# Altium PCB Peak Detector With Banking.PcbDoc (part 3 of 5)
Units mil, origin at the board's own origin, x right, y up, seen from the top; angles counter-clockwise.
Board outline 3330 x 2725 mil, 4 copper layers (TopLayer, GROUND, MidLayer1, BottomLayer); 549 components, 391 nets, 1594 pads, 460 vias.
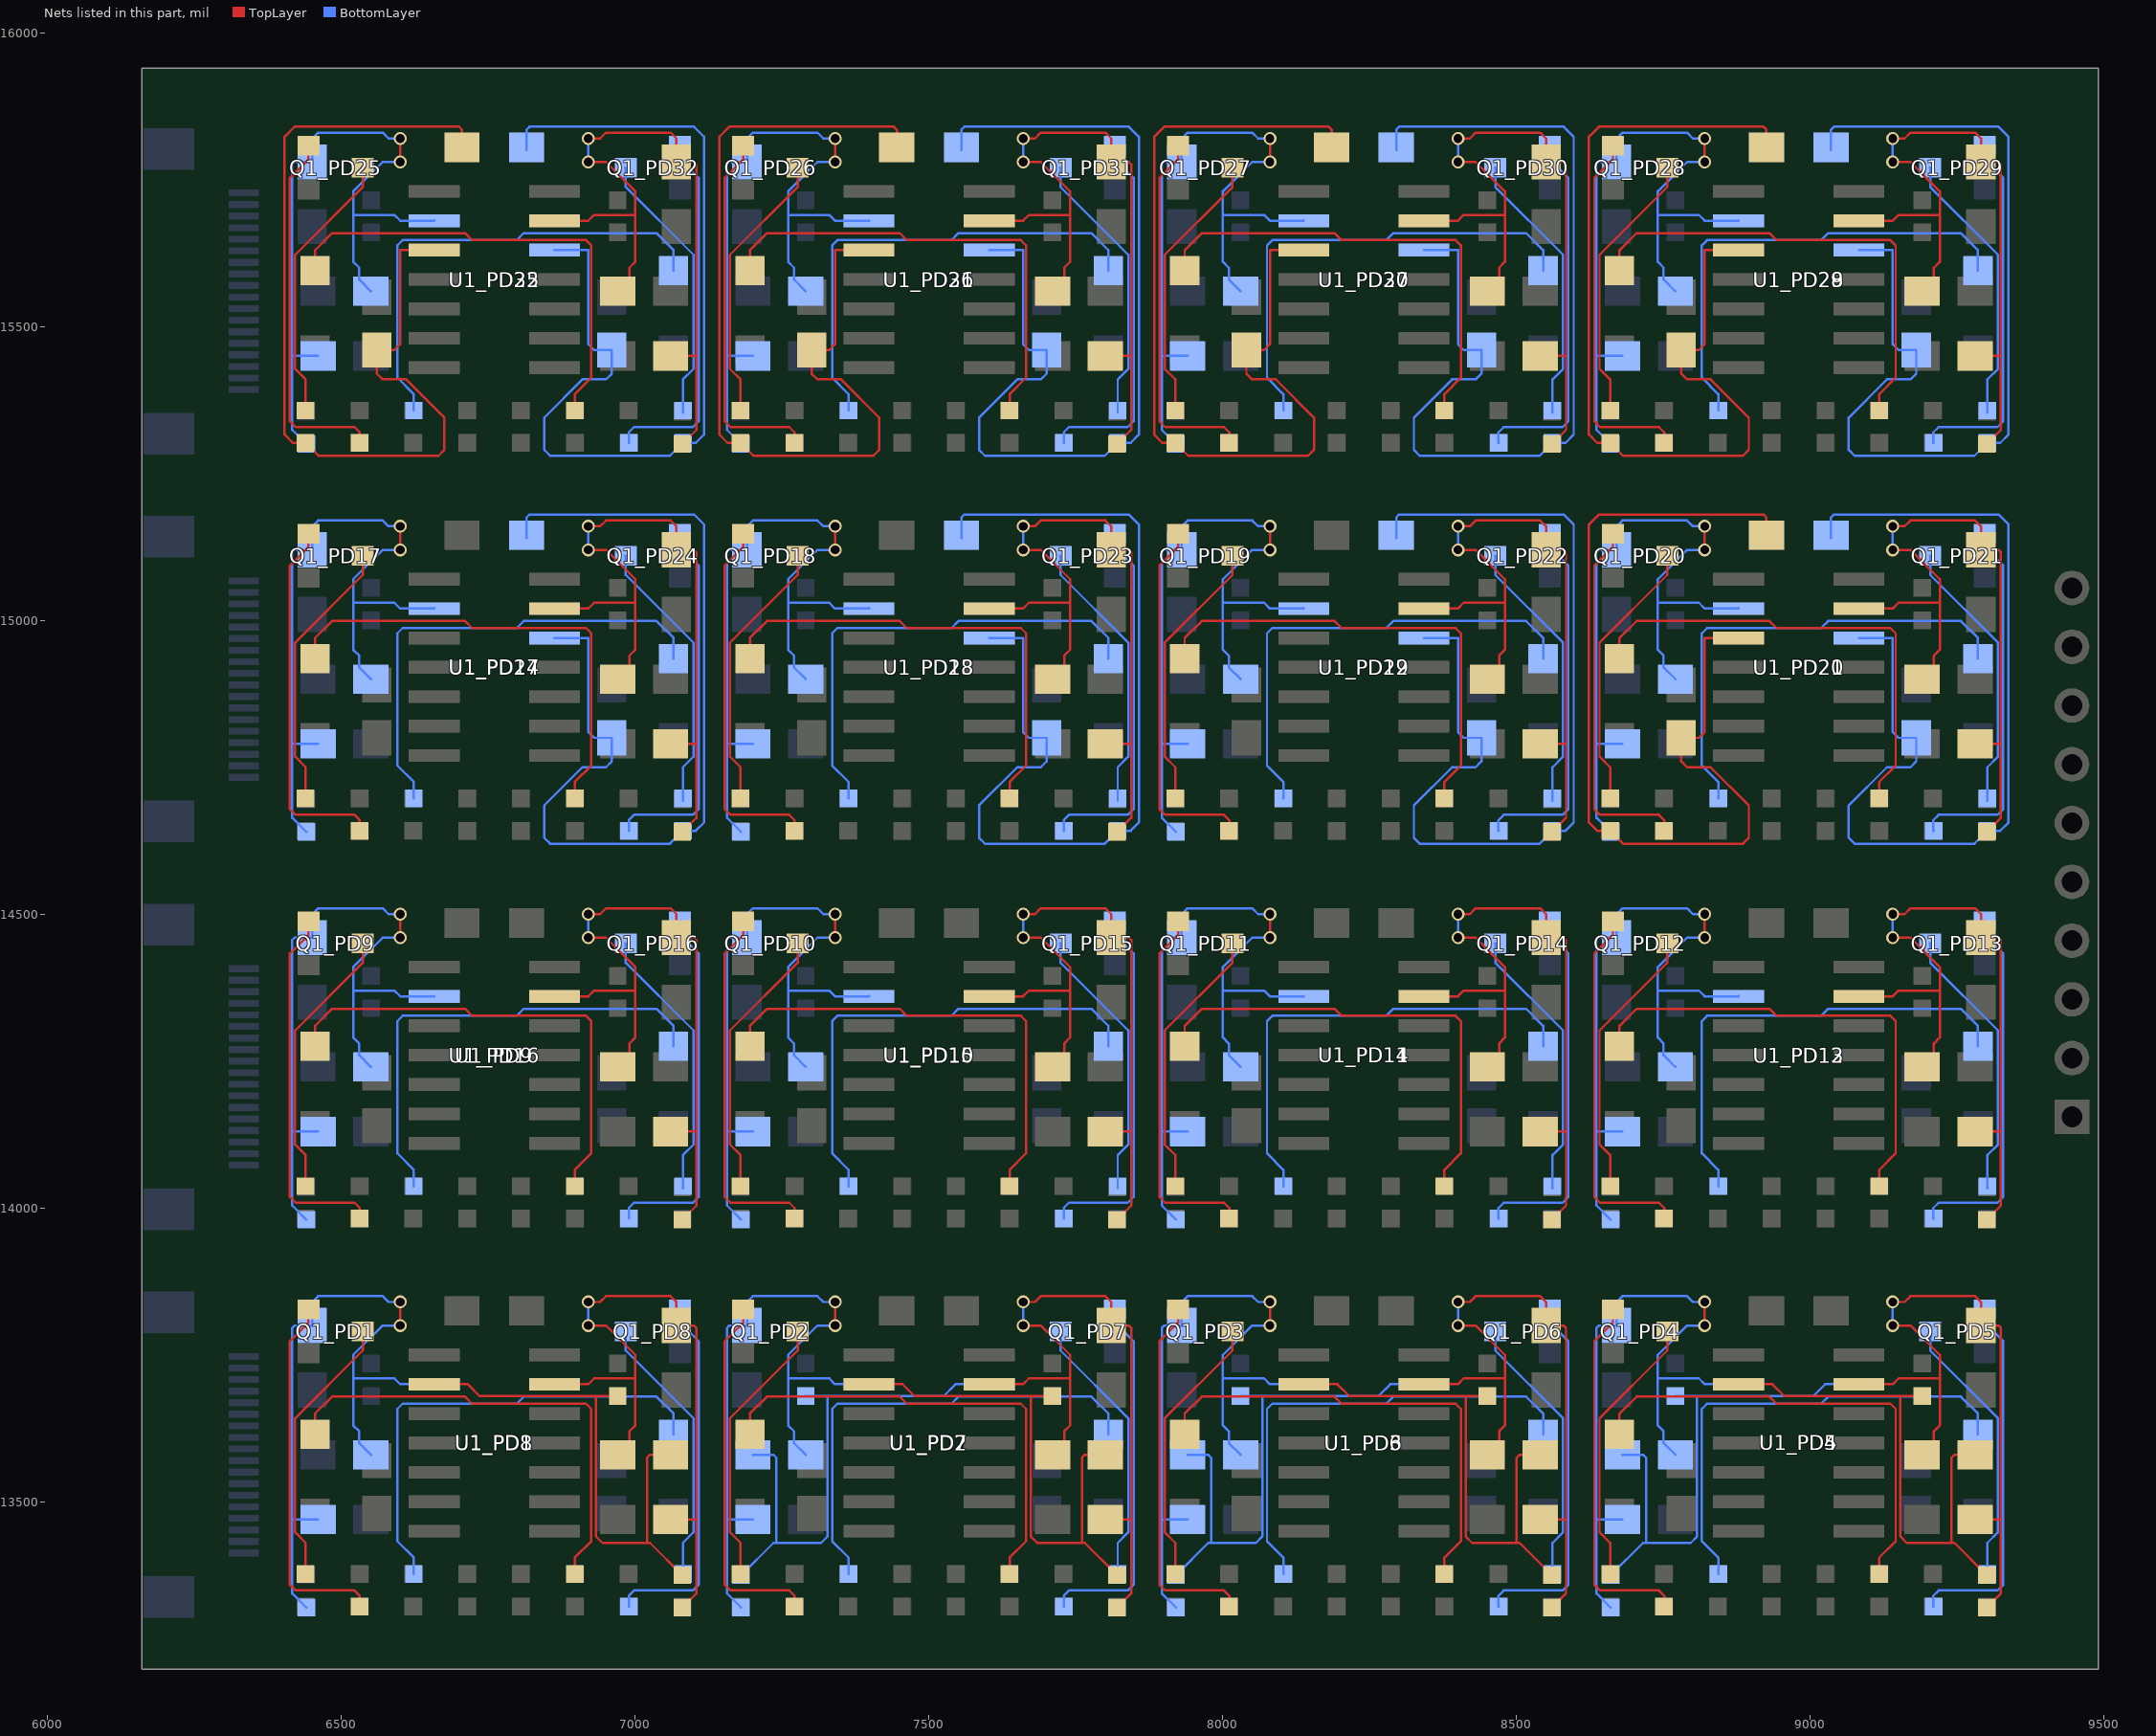
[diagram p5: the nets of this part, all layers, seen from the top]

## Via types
v1: diameter 22, hole 15, TopLayer to BottomLayer, 432 vias
v2: diameter 22, hole 16, TopLayer to BottomLayer, 28 vias

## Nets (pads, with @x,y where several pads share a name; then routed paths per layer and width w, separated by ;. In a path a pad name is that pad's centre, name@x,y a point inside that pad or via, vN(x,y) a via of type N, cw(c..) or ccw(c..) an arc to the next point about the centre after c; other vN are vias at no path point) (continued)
N6_PD20: C6_PD20.2 D1_PD20.2 R5_PD20.1 U1_PD20.10 | length 1647
  TopLayer w4: U1_PD20.10@8877.63,14970 8820,14970 8820,14810 8810,14800 C6_PD20.2@8780,14799.99 8780,14760 8790,14750 8830,14750 8895,14685 8895,14630 8885,14620 8681,14620 R5_PD20.1@8659,14642 8637,14642 8623,14656 8623,15163 8640,15180 8920,15180 8925.01,15174.99 D1_PD20.2@8925.01,15145 D1_PD20.2@8925.01,15140
N6_PD21: C6_PD21.2 D1_PD21.2 R5_PD21.1 U1_PD21.10 | length 1647
  BottomLayer w4: D1_PD21.2@9034.99,15140 D1_PD21.2@9034.99,15145 9034.99,15174.99 9040,15180 9320,15180 9337,15163 9337,14656 9323,14642 R5_PD21.1@9301,14642 9279,14620 9075,14620 9065,14630 9065,14685 9130,14750 9170,14750 9180,14760 C6_PD21.2@9180,14799.99 9150,14800 9140,14810 9140,14970 U1_PD21.10@9082.37,14970
N6_PD22: C6_PD22.2 D1_PD22.2 R5_PD22.1 U1_PD22.10 | length 1647
  BottomLayer w4: D1_PD22.2@8294.99,15140 D1_PD22.2@8294.99,15145 8294.99,15174.99 8300,15180 8580,15180 8597,15163 8597,14656 8583,14642 R5_PD22.1@8561,14642 8539,14620 8335,14620 8325,14630 8325,14685 8390,14750 8430,14750 8440,14760 C6_PD22.2@8440,14799.99 8410,14800 8400,14810 8400,14970 U1_PD22.10@8342.37,14970
N6_PD23: C6_PD23.2 D1_PD23.2 R5_PD23.1 U1_PD23.10 | length 1647
  BottomLayer w4: D1_PD23.2@7554.99,15140 D1_PD23.2@7554.99,15145 7554.99,15174.99 7560,15180 7840,15180 7857,15163 7857,14656 7843,14642 R5_PD23.1@7821,14642 7799,14620 7595,14620 7585,14630 7585,14685 7650,14750 7690,14750 7700,14760 C6_PD23.2@7700,14799.99 7670,14800 7660,14810 7660,14970 U1_PD23.10@7602.37,14970
N6_PD24: C6_PD24.2 D1_PD24.2 R5_PD24.1 U1_PD24.10 | length 1647
  BottomLayer w4: D1_PD24.2@6814.99,15140 D1_PD24.2@6814.99,15145 6814.99,15174.99 6820,15180 7100,15180 7117,15163 7117,14656 7103,14642 R5_PD24.1@7081,14642 7059,14620 6855,14620 6845,14630 6845,14685 6910,14750 6950,14750 6960,14760 C6_PD24.2@6960,14799.99 6930,14800 6920,14810 6920,14970 U1_PD24.10@6862.37,14970
N6_PD25: C6_PD25.2 D1_PD25.2 R5_PD25.1 U1_PD25.10 | length 1647
  TopLayer w4: U1_PD25.10@6657.63,15630 6600,15630 6600,15470 6590,15460 C6_PD25.2@6560,15459.99 6560,15420 6570,15410 6610,15410 6675,15345 6675,15290 6665,15280 6461,15280 R5_PD25.1@6439,15302 6417,15302 6403,15316 6403,15823 6420,15840 6700,15840 6705.01,15834.99 D1_PD25.2@6705.01,15805 D1_PD25.2@6705.01,15800
N6_PD26: C6_PD26.2 D1_PD26.2 R5_PD26.1 U1_PD26.10 | length 1647
  TopLayer w4: U1_PD26.10@7397.63,15630 7340,15630 7340,15470 7330,15460 C6_PD26.2@7300,15459.99 7300,15420 7310,15410 7350,15410 7415,15345 7415,15290 7405,15280 7201,15280 R5_PD26.1@7179,15302 7157,15302 7143,15316 7143,15823 7160,15840 7440,15840 7445.01,15834.99 D1_PD26.2@7445.01,15805 D1_PD26.2@7445.01,15800
N6_PD27: C6_PD27.2 D1_PD27.2 R5_PD27.1 U1_PD27.10 | length 1647
  TopLayer w4: U1_PD27.10@8137.63,15630 8080,15630 8080,15470 8070,15460 C6_PD27.2@8040,15459.99 8040,15420 8050,15410 8090,15410 8155,15345 8155,15290 8145,15280 7941,15280 R5_PD27.1@7919,15302 7897,15302 7883,15316 7883,15823 7900,15840 8180,15840 8185.01,15834.99 D1_PD27.2@8185.01,15805 D1_PD27.2@8185.01,15800
N6_PD28: C6_PD28.2 D1_PD28.2 R5_PD28.1 U1_PD28.10 | length 1647
  TopLayer w4: U1_PD28.10@8877.63,15630 8820,15630 8820,15470 8810,15460 C6_PD28.2@8780,15459.99 8780,15420 8790,15410 8830,15410 8895,15345 8895,15290 8885,15280 8681,15280 R5_PD28.1@8659,15302 8637,15302 8623,15316 8623,15823 8640,15840 8920,15840 8925.01,15834.99 D1_PD28.2@8925.01,15805 D1_PD28.2@8925.01,15800
N6_PD29: C6_PD29.2 D1_PD29.2 R5_PD29.1 U1_PD29.10 | length 1647
  BottomLayer w4: D1_PD29.2@9034.99,15800 D1_PD29.2@9034.99,15805 9034.99,15834.99 9040,15840 9320,15840 9337,15823 9337,15316 9323,15302 R5_PD29.1@9301,15302 9279,15280 9075,15280 9065,15290 9065,15345 9130,15410 9170,15410 9180,15420 C6_PD29.2@9180,15459.99 9150,15460 9140,15470 9140,15630 U1_PD29.10@9082.37,15630
N6_PD30: C6_PD30.2 D1_PD30.2 R5_PD30.1 U1_PD30.10 | length 1647
  BottomLayer w4: D1_PD30.2@8294.99,15800 D1_PD30.2@8294.99,15805 8294.99,15834.99 8300,15840 8580,15840 8597,15823 8597,15316 8583,15302 R5_PD30.1@8561,15302 8539,15280 8335,15280 8325,15290 8325,15345 8390,15410 8430,15410 8440,15420 C6_PD30.2@8440,15459.99 8410,15460 8400,15470 8400,15630 U1_PD30.10@8342.37,15630
N6_PD31: C6_PD31.2 D1_PD31.2 R5_PD31.1 U1_PD31.10 | length 1647
  BottomLayer w4: D1_PD31.2@7554.99,15800 D1_PD31.2@7554.99,15805 7554.99,15834.99 7560,15840 7840,15840 7857,15823 7857,15316 7843,15302 R5_PD31.1@7821,15302 7799,15280 7595,15280 7585,15290 7585,15345 7650,15410 7690,15410 7700,15420 C6_PD31.2@7700,15459.99 7670,15460 7660,15470 7660,15630 U1_PD31.10@7602.37,15630
N6_PD32: C6_PD32.2 D1_PD32.2 R5_PD32.1 U1_PD32.10 | length 1647
  BottomLayer w4: D1_PD32.2@6814.99,15800 D1_PD32.2@6814.99,15805 6814.99,15834.99 6820,15840 7100,15840 7117,15823 7117,15316 7103,15302 R5_PD32.1@7081,15302 7059,15280 6855,15280 6845,15290 6845,15345 6910,15410 6950,15410 6960,15420 C6_PD32.2@6960,15459.99 6930,15460 6920,15470 6920,15630 U1_PD32.10@6862.37,15630
N7_PD1: Q1_PD1.2 R4_PD1.2 | length 626.9
  TopLayer w4: Q1_PD1.2@6443.74,13827.4 6443.74,13804.74 6412,13773 6412,13359 6422,13349 6522,13349 6531,13340 6531,13321.99 R4_PD1.2@6530.57,13321.99
N7_PD2: Q1_PD2.2 R4_PD2.2 | length 626.9
  TopLayer w4: Q1_PD2.2@7183.74,13827.4 7183.74,13804.74 7152,13773 7152,13359 7162,13349 7262,13349 7271,13340 7271,13321.99 R4_PD2.2@7270.57,13321.99
N7_PD3: Q1_PD3.2 R4_PD3.2 | length 626.9
  TopLayer w4: Q1_PD3.2@7923.74,13827.4 7923.74,13804.74 7892,13773 7892,13359 7902,13349 8002,13349 8011,13340 8011,13321.99 R4_PD3.2@8010.57,13321.99
N7_PD4: Q1_PD4.2 R4_PD4.2 | length 626.9
  TopLayer w4: Q1_PD4.2@8663.74,13827.4 8663.74,13804.74 8632,13773 8632,13359 8642,13349 8742,13349 8751,13340 8751,13321.99 R4_PD4.2@8750.57,13321.99
N7_PD5: Q1_PD5.2 R4_PD5.2 | length 626.9
  BottomLayer w4: R4_PD5.2@9209.43,13321.99 9209,13321.99 9209,13340 9218,13349 9318,13349 9328,13359 9328,13773 9296.26,13804.74 Q1_PD5.2@9296.26,13827.4
N7_PD6: Q1_PD6.2 R4_PD6.2 | length 626.9
  BottomLayer w4: R4_PD6.2@8469.43,13321.99 8469,13321.99 8469,13340 8478,13349 8578,13349 8588,13359 8588,13773 8556.26,13804.74 Q1_PD6.2@8556.26,13827.4
N7_PD7: Q1_PD7.2 R4_PD7.2 | length 626.9
  BottomLayer w4: R4_PD7.2@7729.43,13321.99 7729,13321.99 7729,13340 7738,13349 7838,13349 7848,13359 7848,13773 7816.26,13804.74 Q1_PD7.2@7816.26,13827.4
N7_PD8: Q1_PD8.2 R4_PD8.2 | length 626.9
  BottomLayer w4: R4_PD8.2@6989.43,13321.99 6989,13321.99 6989,13340 6998,13349 7098,13349 7108,13359 7108,13773 7076.26,13804.74 Q1_PD8.2@7076.26,13827.4
N7_PD9: Q1_PD9.2 R4_PD9.2 | length 626.9
  TopLayer w4: Q1_PD9.2@6443.74,14487.4 6443.74,14464.74 6412,14433 6412,14019 6422,14009 6522,14009 6531,14000 6531,13981.99 R4_PD9.2@6530.57,13981.99
N7_PD10: Q1_PD10.2 R4_PD10.2 | length 626.9
  TopLayer w4: Q1_PD10.2@7183.74,14487.4 7183.74,14464.74 7152,14433 7152,14019 7162,14009 7262,14009 7271,14000 7271,13981.99 R4_PD10.2@7270.57,13981.99
N7_PD11: Q1_PD11.2 R4_PD11.2 | length 626.9
  TopLayer w4: Q1_PD11.2@7923.74,14487.4 7923.74,14464.74 7892,14433 7892,14019 7902,14009 8002,14009 8011,14000 8011,13981.99 R4_PD11.2@8010.57,13981.99
N7_PD12: Q1_PD12.2 R4_PD12.2 | length 626.9
  TopLayer w4: Q1_PD12.2@8663.74,14487.4 8663.74,14464.74 8632,14433 8632,14019 8642,14009 8742,14009 8751,14000 8751,13981.99 R4_PD12.2@8750.57,13981.99
N7_PD13: Q1_PD13.2 R4_PD13.2 | length 626.9
  BottomLayer w4: R4_PD13.2@9209.43,13981.99 9209,13981.99 9209,14000 9218,14009 9318,14009 9328,14019 9328,14433 9296.26,14464.74 Q1_PD13.2@9296.26,14487.4
N7_PD14: Q1_PD14.2 R4_PD14.2 | length 626.9
  BottomLayer w4: R4_PD14.2@8469.43,13981.99 8469,13981.99 8469,14000 8478,14009 8578,14009 8588,14019 8588,14433 8556.26,14464.74 Q1_PD14.2@8556.26,14487.4
N7_PD15: Q1_PD15.2 R4_PD15.2 | length 626.9
  BottomLayer w4: R4_PD15.2@7729.43,13981.99 7729,13981.99 7729,14000 7738,14009 7838,14009 7848,14019 7848,14433 7816.26,14464.74 Q1_PD15.2@7816.26,14487.4
N7_PD16: Q1_PD16.2 R4_PD16.2 | length 626.9
  BottomLayer w4: R4_PD16.2@6989.43,13981.99 6989,13981.99 6989,14000 6998,14009 7098,14009 7108,14019 7108,14433 7076.26,14464.74 Q1_PD16.2@7076.26,14487.4
N7_PD17: Q1_PD17.2 R4_PD17.2 | length 626.9
  TopLayer w4: Q1_PD17.2@6443.74,15147.4 6443.74,15124.74 6412,15093 6412,14679 6422,14669 6522,14669 6531,14660 6531,14641.99 R4_PD17.2@6530.57,14641.99
N7_PD18: Q1_PD18.2 R4_PD18.2 | length 626.9
  TopLayer w4: Q1_PD18.2@7183.74,15147.4 7183.74,15124.74 7152,15093 7152,14679 7162,14669 7262,14669 7271,14660 7271,14641.99 R4_PD18.2@7270.57,14641.99
N7_PD19: Q1_PD19.2 R4_PD19.2 | length 626.9
  TopLayer w4: Q1_PD19.2@7923.74,15147.4 7923.74,15124.74 7892,15093 7892,14679 7902,14669 8002,14669 8011,14660 8011,14641.99 R4_PD19.2@8010.57,14641.99
N7_PD20: Q1_PD20.2 R4_PD20.2 | length 626.9
  TopLayer w4: Q1_PD20.2@8663.74,15147.4 8663.74,15124.74 8632,15093 8632,14679 8642,14669 8742,14669 8751,14660 8751,14641.99 R4_PD20.2@8750.57,14641.99
N7_PD21: Q1_PD21.2 R4_PD21.2 | length 626.9
  BottomLayer w4: R4_PD21.2@9209.43,14641.99 9209,14641.99 9209,14660 9218,14669 9318,14669 9328,14679 9328,15093 9296.26,15124.74 Q1_PD21.2@9296.26,15147.4
N7_PD22: Q1_PD22.2 R4_PD22.2 | length 626.9
  BottomLayer w4: R4_PD22.2@8469.43,14641.99 8469,14641.99 8469,14660 8478,14669 8578,14669 8588,14679 8588,15093 8556.26,15124.74 Q1_PD22.2@8556.26,15147.4
N7_PD23: Q1_PD23.2 R4_PD23.2 | length 626.9
  BottomLayer w4: R4_PD23.2@7729.43,14641.99 7729,14641.99 7729,14660 7738,14669 7838,14669 7848,14679 7848,15093 7816.26,15124.74 Q1_PD23.2@7816.26,15147.4
N7_PD24: Q1_PD24.2 R4_PD24.2 | length 626.9
  BottomLayer w4: R4_PD24.2@6989.43,14641.99 6989,14641.99 6989,14660 6998,14669 7098,14669 7108,14679 7108,15093 7076.26,15124.74 Q1_PD24.2@7076.26,15147.4
N7_PD25: Q1_PD25.2 R4_PD25.2 | length 626.9
  TopLayer w4: Q1_PD25.2@6443.74,15807.4 6443.74,15784.74 6412,15753 6412,15339 6422,15329 6522,15329 6531,15320 6531,15301.99 R4_PD25.2@6530.57,15301.99
N7_PD26: Q1_PD26.2 R4_PD26.2 | length 626.9
  TopLayer w4: Q1_PD26.2@7183.74,15807.4 7183.74,15784.74 7152,15753 7152,15339 7162,15329 7262,15329 7271,15320 7271,15301.99 R4_PD26.2@7270.57,15301.99
N7_PD27: Q1_PD27.2 R4_PD27.2 | length 626.9
  TopLayer w4: Q1_PD27.2@7923.74,15807.4 7923.74,15784.74 7892,15753 7892,15339 7902,15329 8002,15329 8011,15320 8011,15301.99 R4_PD27.2@8010.57,15301.99
N7_PD28: Q1_PD28.2 R4_PD28.2 | length 626.9
  TopLayer w4: Q1_PD28.2@8663.74,15807.4 8663.74,15784.74 8632,15753 8632,15339 8642,15329 8742,15329 8751,15320 8751,15301.99 R4_PD28.2@8750.57,15301.99
N7_PD29: Q1_PD29.2 R4_PD29.2 | length 626.9
  BottomLayer w4: R4_PD29.2@9209.43,15301.99 9209,15301.99 9209,15320 9218,15329 9318,15329 9328,15339 9328,15753 9296.26,15784.74 Q1_PD29.2@9296.26,15807.4
N7_PD30: Q1_PD30.2 R4_PD30.2 | length 626.9
  BottomLayer w4: R4_PD30.2@8469.43,15301.99 8469,15301.99 8469,15320 8478,15329 8578,15329 8588,15339 8588,15753 8556.26,15784.74 Q1_PD30.2@8556.26,15807.4
N7_PD31: Q1_PD31.2 R4_PD31.2 | length 626.9
  BottomLayer w4: R4_PD31.2@7729.43,15301.99 7729,15301.99 7729,15320 7738,15329 7838,15329 7848,15339 7848,15753 7816.26,15784.74 Q1_PD31.2@7816.26,15807.4
N7_PD32: Q1_PD32.2 R4_PD32.2 | length 626.9
  BottomLayer w4: R4_PD32.2@6989.43,15301.99 6989,15301.99 6989,15320 6998,15329 7098,15329 7108,15339 7108,15753 7076.26,15784.74 Q1_PD32.2@7076.26,15807.4
N8_PD1: Q1_PD1.1 R5_PD1.2 | length 472.9
  TopLayer w4: R5_PD1.2@6439,13373 R5_PD1.2@6439,13377 6439,13430 6421,13448 6421,13642 6536.26,13757.26 Q1_PD1.1@6536.26,13790 Q1_PD1.1@6537,13790
N8_PD2: Q1_PD2.1 R5_PD2.2 | length 472.9
  TopLayer w4: R5_PD2.2@7179,13373 R5_PD2.2@7179,13377 7179,13430 7161,13448 7161,13642 7276.26,13757.26 Q1_PD2.1@7276.26,13790 Q1_PD2.1@7277,13790
N8_PD3: Q1_PD3.1 R5_PD3.2 | length 472.9
  TopLayer w4: R5_PD3.2@7919,13373 R5_PD3.2@7919,13377 7919,13430 7901,13448 7901,13642 8016.26,13757.26 Q1_PD3.1@8016.26,13790 Q1_PD3.1@8017,13790
N8_PD4: Q1_PD4.1 R5_PD4.2 | length 472.9
  TopLayer w4: R5_PD4.2@8659,13373 R5_PD4.2@8659,13377 8659,13430 8641,13448 8641,13642 8756.26,13757.26 Q1_PD4.1@8756.26,13790 Q1_PD4.1@8757,13790
N8_PD5: Q1_PD5.1 R5_PD5.2 | length 472.9
  BottomLayer w4: Q1_PD5.1@9203,13790 Q1_PD5.1@9203.74,13790 9203.74,13757.26 9319,13642 9319,13448 9301,13430 R5_PD5.2@9301,13377 R5_PD5.2@9301,13373
N8_PD6: Q1_PD6.1 R5_PD6.2 | length 472.9
  BottomLayer w4: Q1_PD6.1@8463,13790 Q1_PD6.1@8463.74,13790 8463.74,13757.26 8579,13642 8579,13448 8561,13430 R5_PD6.2@8561,13377 R5_PD6.2@8561,13373
N8_PD7: Q1_PD7.1 R5_PD7.2 | length 472.9
  BottomLayer w4: Q1_PD7.1@7723,13790 Q1_PD7.1@7723.74,13790 7723.74,13757.26 7839,13642 7839,13448 7821,13430 R5_PD7.2@7821,13377 R5_PD7.2@7821,13373
N8_PD8: Q1_PD8.1 R5_PD8.2 | length 472.9
  BottomLayer w4: Q1_PD8.1@6983,13790 Q1_PD8.1@6983.74,13790 6983.74,13757.26 7099,13642 7099,13448 7081,13430 R5_PD8.2@7081,13377 R5_PD8.2@7081,13373
N8_PD9: Q1_PD9.1 R5_PD9.2 | length 472.9
  TopLayer w4: R5_PD9.2@6439,14033 R5_PD9.2@6439,14037 6439,14090 6421,14108 6421,14302 6536.26,14417.26 Q1_PD9.1@6536.26,14450 Q1_PD9.1@6537,14450
N8_PD10: Q1_PD10.1 R5_PD10.2 | length 472.9
  TopLayer w4: R5_PD10.2@7179,14033 R5_PD10.2@7179,14037 7179,14090 7161,14108 7161,14302 7276.26,14417.26 Q1_PD10.1@7276.26,14450 Q1_PD10.1@7277,14450
N8_PD11: Q1_PD11.1 R5_PD11.2 | length 472.9
  TopLayer w4: R5_PD11.2@7919,14033 R5_PD11.2@7919,14037 7919,14090 7901,14108 7901,14302 8016.26,14417.26 Q1_PD11.1@8016.26,14450 Q1_PD11.1@8017,14450
N8_PD12: Q1_PD12.1 R5_PD12.2 | length 472.9
  TopLayer w4: R5_PD12.2@8659,14033 R5_PD12.2@8659,14037 8659,14090 8641,14108 8641,14302 8756.26,14417.26 Q1_PD12.1@8756.26,14450 Q1_PD12.1@8757,14450
N8_PD13: Q1_PD13.1 R5_PD13.2 | length 472.9
  BottomLayer w4: Q1_PD13.1@9203,14450 Q1_PD13.1@9203.74,14450 9203.74,14417.26 9319,14302 9319,14108 9301,14090 R5_PD13.2@9301,14037 R5_PD13.2@9301,14033
N8_PD14: Q1_PD14.1 R5_PD14.2 | length 472.9
  BottomLayer w4: Q1_PD14.1@8463,14450 Q1_PD14.1@8463.74,14450 8463.74,14417.26 8579,14302 8579,14108 8561,14090 R5_PD14.2@8561,14037 R5_PD14.2@8561,14033
N8_PD15: Q1_PD15.1 R5_PD15.2 | length 472.9
  BottomLayer w4: Q1_PD15.1@7723,14450 Q1_PD15.1@7723.74,14450 7723.74,14417.26 7839,14302 7839,14108 7821,14090 R5_PD15.2@7821,14037 R5_PD15.2@7821,14033
N8_PD16: Q1_PD16.1 R5_PD16.2 | length 472.9
  BottomLayer w4: Q1_PD16.1@6983,14450 Q1_PD16.1@6983.74,14450 6983.74,14417.26 7099,14302 7099,14108 7081,14090 R5_PD16.2@7081,14037 R5_PD16.2@7081,14033
N8_PD17: Q1_PD17.1 R5_PD17.2 | length 472.9
  TopLayer w4: R5_PD17.2@6439,14693 R5_PD17.2@6439,14697 6439,14750 6421,14768 6421,14962 6536.26,15077.26 Q1_PD17.1@6536.26,15110 Q1_PD17.1@6537,15110
N8_PD18: Q1_PD18.1 R5_PD18.2 | length 472.9
  TopLayer w4: R5_PD18.2@7179,14693 R5_PD18.2@7179,14697 7179,14750 7161,14768 7161,14962 7276.26,15077.26 Q1_PD18.1@7276.26,15110 Q1_PD18.1@7277,15110
N8_PD19: Q1_PD19.1 R5_PD19.2 | length 472.9
  TopLayer w4: R5_PD19.2@7919,14693 R5_PD19.2@7919,14697 7919,14750 7901,14768 7901,14962 8016.26,15077.26 Q1_PD19.1@8016.26,15110 Q1_PD19.1@8017,15110
N8_PD20: Q1_PD20.1 R5_PD20.2 | length 472.9
  TopLayer w4: R5_PD20.2@8659,14693 R5_PD20.2@8659,14697 8659,14750 8641,14768 8641,14962 8756.26,15077.26 Q1_PD20.1@8756.26,15110 Q1_PD20.1@8757,15110
N8_PD21: Q1_PD21.1 R5_PD21.2 | length 472.9
  BottomLayer w4: Q1_PD21.1@9203,15110 Q1_PD21.1@9203.74,15110 9203.74,15077.26 9319,14962 9319,14768 9301,14750 R5_PD21.2@9301,14697 R5_PD21.2@9301,14693
N8_PD22: Q1_PD22.1 R5_PD22.2 | length 472.9
  BottomLayer w4: Q1_PD22.1@8463,15110 Q1_PD22.1@8463.74,15110 8463.74,15077.26 8579,14962 8579,14768 8561,14750 R5_PD22.2@8561,14697 R5_PD22.2@8561,14693
N8_PD23: Q1_PD23.1 R5_PD23.2 | length 472.9
  BottomLayer w4: Q1_PD23.1@7723,15110 Q1_PD23.1@7723.74,15110 7723.74,15077.26 7839,14962 7839,14768 7821,14750 R5_PD23.2@7821,14697 R5_PD23.2@7821,14693
N8_PD24: Q1_PD24.1 R5_PD24.2 | length 472.9
  BottomLayer w4: Q1_PD24.1@6983,15110 Q1_PD24.1@6983.74,15110 6983.74,15077.26 7099,14962 7099,14768 7081,14750 R5_PD24.2@7081,14697 R5_PD24.2@7081,14693
N8_PD25: Q1_PD25.1 R5_PD25.2 | length 472.9
  TopLayer w4: R5_PD25.2@6439,15353 R5_PD25.2@6439,15357 6439,15410 6421,15428 6421,15622 6536.26,15737.26 Q1_PD25.1@6536.26,15770 Q1_PD25.1@6537,15770
N8_PD26: Q1_PD26.1 R5_PD26.2 | length 472.9
  TopLayer w4: R5_PD26.2@7179,15353 R5_PD26.2@7179,15357 7179,15410 7161,15428 7161,15622 7276.26,15737.26 Q1_PD26.1@7276.26,15770 Q1_PD26.1@7277,15770
N8_PD27: Q1_PD27.1 R5_PD27.2 | length 472.9
  TopLayer w4: R5_PD27.2@7919,15353 R5_PD27.2@7919,15357 7919,15410 7901,15428 7901,15622 8016.26,15737.26 Q1_PD27.1@8016.26,15770 Q1_PD27.1@8017,15770
N8_PD28: Q1_PD28.1 R5_PD28.2 | length 472.9
  TopLayer w4: R5_PD28.2@8659,15353 R5_PD28.2@8659,15357 8659,15410 8641,15428 8641,15622 8756.26,15737.26 Q1_PD28.1@8756.26,15770 Q1_PD28.1@8757,15770
N8_PD29: Q1_PD29.1 R5_PD29.2 | length 472.9
  BottomLayer w4: Q1_PD29.1@9203,15770 Q1_PD29.1@9203.74,15770 9203.74,15737.26 9319,15622 9319,15428 9301,15410 R5_PD29.2@9301,15357 R5_PD29.2@9301,15353
N8_PD30: Q1_PD30.1 R5_PD30.2 | length 472.9
  BottomLayer w4: Q1_PD30.1@8463,15770 Q1_PD30.1@8463.74,15770 8463.74,15737.26 8579,15622 8579,15428 8561,15410 R5_PD30.2@8561,15357 R5_PD30.2@8561,15353
N8_PD31: Q1_PD31.1 R5_PD31.2 | length 472.9
  BottomLayer w4: Q1_PD31.1@7723,15770 Q1_PD31.1@7723.74,15770 7723.74,15737.26 7839,15622 7839,15428 7821,15410 R5_PD31.2@7821,15357 R5_PD31.2@7821,15353
N8_PD32: Q1_PD32.1 R5_PD32.2 | length 472.9
  BottomLayer w4: Q1_PD32.1@6983,15770 Q1_PD32.1@6983.74,15770 6983.74,15737.26 7099,15622 7099,15428 7081,15410 R5_PD32.2@7081,15357 R5_PD32.2@7081,15353
NetC1_PD1_1: C1_PD1.1 R1_PD1.1 | length 818.5
  TopLayer w4: C1_PD1.1@6455,13615 6455,13650 6484,13679 6710,13679 6722,13667 6916,13667 6925,13658 6925,13433 6897,13405 6897,13376.99 R1_PD1.1@6896.86,13376.99
NetC1_PD2_1: C1_PD2.1 R1_PD2.1 | length 818.5
  TopLayer w4: C1_PD2.1@7195,13615 7195,13650 7224,13679 7450,13679 7462,13667 7656,13667 7665,13658 7665,13433 7637,13405 7637,13376.99 R1_PD2.1@7636.86,13376.99
NetC1_PD3_1: C1_PD3.1 R1_PD3.1 | length 818.5
  TopLayer w4: C1_PD3.1@7935,13615 7935,13650 7964,13679 8190,13679 8202,13667 8396,13667 8405,13658 8405,13433 8377,13405 8377,13376.99 R1_PD3.1@8376.86,13376.99
NetC1_PD4_1: C1_PD4.1 R1_PD4.1 | length 818.5
  TopLayer w4: C1_PD4.1@8675,13615 8675,13650 8704,13679 8930,13679 8942,13667 9136,13667 9145,13658 9145,13433 9117,13405 9117,13376.99 R1_PD4.1@9116.86,13376.99
NetC1_PD5_1: C1_PD5.1 R1_PD5.1 | length 818.5
  BottomLayer w4: R1_PD5.1@8843.14,13376.99 8843,13376.99 8843,13405 8815,13433 8815,13658 8824,13667 9018,13667 9030,13679 9256,13679 9285,13650 C1_PD5.1@9285,13615
NetC1_PD6_1: C1_PD6.1 R1_PD6.1 | length 818.5
  BottomLayer w4: R1_PD6.1@8103.14,13376.99 8103,13376.99 8103,13405 8075,13433 8075,13658 8084,13667 8278,13667 8290,13679 8516,13679 8545,13650 C1_PD6.1@8545,13615
NetC1_PD7_1: C1_PD7.1 R1_PD7.1 | length 818.5
  BottomLayer w4: R1_PD7.1@7363.14,13376.99 7363,13376.99 7363,13405 7335,13433 7335,13658 7344,13667 7538,13667 7550,13679 7776,13679 7805,13650 C1_PD7.1@7805,13615
NetC1_PD8_1: C1_PD8.1 R1_PD8.1 | length 818.5
  BottomLayer w4: R1_PD8.1@6623.14,13376.99 6623,13376.99 6623,13405 6595,13433 6595,13658 6604,13667 6798,13667 6810,13679 7036,13679 7065,13650 C1_PD8.1@7065,13615
NetC1_PD9_1: C1_PD9.1 R1_PD9.1 | length 818.5
  TopLayer w4: C1_PD9.1@6455,14275 6455,14310 6484,14339 6710,14339 6722,14327 6916,14327 6925,14318 6925,14093 6897,14065 6897,14036.99 R1_PD9.1@6896.86,14036.99
NetC1_PD10_1: C1_PD10.1 R1_PD10.1 | length 818.5
  TopLayer w4: C1_PD10.1@7195,14275 7195,14310 7224,14339 7450,14339 7462,14327 7656,14327 7665,14318 7665,14093 7637,14065 7637,14036.99 R1_PD10.1@7636.86,14036.99
NetC1_PD11_1: C1_PD11.1 R1_PD11.1 | length 818.5
  TopLayer w4: C1_PD11.1@7935,14275 7935,14310 7964,14339 8190,14339 8202,14327 8396,14327 8405,14318 8405,14093 8377,14065 8377,14036.99 R1_PD11.1@8376.86,14036.99
NetC1_PD12_1: C1_PD12.1 R1_PD12.1 | length 818.5
  TopLayer w4: C1_PD12.1@8675,14275 8675,14310 8704,14339 8930,14339 8942,14327 9136,14327 9145,14318 9145,14093 9117,14065 9117,14036.99 R1_PD12.1@9116.86,14036.99
NetC1_PD13_1: C1_PD13.1 R1_PD13.1 | length 818.5
  BottomLayer w4: R1_PD13.1@8843.14,14036.99 8843,14036.99 8843,14065 8815,14093 8815,14318 8824,14327 9018,14327 9030,14339 9256,14339 9285,14310 C1_PD13.1@9285,14275
NetC1_PD14_1: C1_PD14.1 R1_PD14.1 | length 818.5
  BottomLayer w4: R1_PD14.1@8103.14,14036.99 8103,14036.99 8103,14065 8075,14093 8075,14318 8084,14327 8278,14327 8290,14339 8516,14339 8545,14310 C1_PD14.1@8545,14275
NetC1_PD15_1: C1_PD15.1 R1_PD15.1 | length 818.5
  BottomLayer w4: R1_PD15.1@7363.14,14036.99 7363,14036.99 7363,14065 7335,14093 7335,14318 7344,14327 7538,14327 7550,14339 7776,14339 7805,14310 C1_PD15.1@7805,14275
NetC1_PD16_1: C1_PD16.1 R1_PD16.1 | length 818.5
  BottomLayer w4: R1_PD16.1@6623.14,14036.99 6623,14036.99 6623,14065 6595,14093 6595,14318 6604,14327 6798,14327 6810,14339 7036,14339 7065,14310 C1_PD16.1@7065,14275
NetC1_PD17_1: C1_PD17.1 R1_PD17.1 | length 818.5
  TopLayer w4: C1_PD17.1@6455,14935 6455,14970 6484,14999 6710,14999 6722,14987 6916,14987 6925,14978 6925,14753 6897,14725 6897,14696.99 R1_PD17.1@6896.86,14696.99
NetC1_PD18_1: C1_PD18.1 R1_PD18.1 | length 818.5
  TopLayer w4: C1_PD18.1@7195,14935 7195,14970 7224,14999 7450,14999 7462,14987 7656,14987 7665,14978 7665,14753 7637,14725 7637,14696.99 R1_PD18.1@7636.86,14696.99
NetC1_PD19_1: C1_PD19.1 R1_PD19.1 | length 818.5
  TopLayer w4: C1_PD19.1@7935,14935 7935,14970 7964,14999 8190,14999 8202,14987 8396,14987 8405,14978 8405,14753 8377,14725 8377,14696.99 R1_PD19.1@8376.86,14696.99
NetC1_PD20_1: C1_PD20.1 R1_PD20.1 | length 818.5
  TopLayer w4: C1_PD20.1@8675,14935 8675,14970 8704,14999 8930,14999 8942,14987 9136,14987 9145,14978 9145,14753 9117,14725 9117,14696.99 R1_PD20.1@9116.86,14696.99
NetC1_PD21_1: C1_PD21.1 R1_PD21.1 | length 818.5
  BottomLayer w4: R1_PD21.1@8843.14,14696.99 8843,14696.99 8843,14725 8815,14753 8815,14978 8824,14987 9018,14987 9030,14999 9256,14999 9285,14970 C1_PD21.1@9285,14935
NetC1_PD22_1: C1_PD22.1 R1_PD22.1 | length 818.5
  BottomLayer w4: R1_PD22.1@8103.14,14696.99 8103,14696.99 8103,14725 8075,14753 8075,14978 8084,14987 8278,14987 8290,14999 8516,14999 8545,14970 C1_PD22.1@8545,14935
NetC1_PD23_1: C1_PD23.1 R1_PD23.1 | length 818.5
  BottomLayer w4: R1_PD23.1@7363.14,14696.99 7363,14696.99 7363,14725 7335,14753 7335,14978 7344,14987 7538,14987 7550,14999 7776,14999 7805,14970 C1_PD23.1@7805,14935
NetC1_PD24_1: C1_PD24.1 R1_PD24.1 | length 818.5
  BottomLayer w4: R1_PD24.1@6623.14,14696.99 6623,14696.99 6623,14725 6595,14753 6595,14978 6604,14987 6798,14987 6810,14999 7036,14999 7065,14970 C1_PD24.1@7065,14935
NetC1_PD25_1: C1_PD25.1 R1_PD25.1 | length 818.5
  TopLayer w4: C1_PD25.1@6455,15595 6455,15630 6484,15659 6710,15659 6722,15647 6916,15647 6925,15638 6925,15413 6897,15385 6897,15356.99 R1_PD25.1@6896.86,15356.99
NetC1_PD26_1: C1_PD26.1 R1_PD26.1 | length 818.5
  TopLayer w4: C1_PD26.1@7195,15595 7195,15630 7224,15659 7450,15659 7462,15647 7656,15647 7665,15638 7665,15413 7637,15385 7637,15356.99 R1_PD26.1@7636.86,15356.99
NetC1_PD27_1: C1_PD27.1 R1_PD27.1 | length 818.5
  TopLayer w4: C1_PD27.1@7935,15595 7935,15630 7964,15659 8190,15659 8202,15647 8396,15647 8405,15638 8405,15413 8377,15385 8377,15356.99 R1_PD27.1@8376.86,15356.99
NetC1_PD28_1: C1_PD28.1 R1_PD28.1 | length 818.5
  TopLayer w4: C1_PD28.1@8675,15595 8675,15630 8704,15659 8930,15659 8942,15647 9136,15647 9145,15638 9145,15413 9117,15385 9117,15356.99 R1_PD28.1@9116.86,15356.99
NetC1_PD29_1: C1_PD29.1 R1_PD29.1 | length 818.5
  BottomLayer w4: R1_PD29.1@8843.14,15356.99 8843,15356.99 8843,15385 8815,15413 8815,15638 8824,15647 9018,15647 9030,15659 9256,15659 9285,15630 C1_PD29.1@9285,15595
NetC1_PD30_1: C1_PD30.1 R1_PD30.1 | length 818.5
  BottomLayer w4: R1_PD30.1@8103.14,15356.99 8103,15356.99 8103,15385 8075,15413 8075,15638 8084,15647 8278,15647 8290,15659 8516,15659 8545,15630 C1_PD30.1@8545,15595
NetC1_PD31_1: C1_PD31.1 R1_PD31.1 | length 818.5
  BottomLayer w4: R1_PD31.1@7363.14,15356.99 7363,15356.99 7363,15385 7335,15413 7335,15638 7344,15647 7538,15647 7550,15659 7776,15659 7805,15630 C1_PD31.1@7805,15595
NetC1_PD32_1: C1_PD32.1 R1_PD32.1 | length 818.5
  BottomLayer w4: R1_PD32.1@6623.14,15356.99 6623,15356.99 6623,15385 6595,15413 6595,15638 6604,15647 6798,15647 6810,15659 7036,15659 7065,15630 C1_PD32.1@7065,15595
NetC4_PD1_1: C4_PD1.1 C5_PD1.1 D2_PD1.1 R8_PD1.1 U1_PD1.6 | length 1228.8
  TopLayer w4: U1_PD1.6@6862.35,13700 6920,13700 6930,13710 7000,13710 ; v1(6920,13800) 6950,13800 7000,13750 7000,13710 ; v1(6920,13840) 6940,13840 6950,13850 7060,13850 7070,13840 D2_PD1.1@7070,13800.01 7099.99,13800.01 7104,13796 7104,13788 7104,13470 ; C5_PD1.1@6970.01,13580 6990,13600 6990,13620 7000,13630 7000,13710 ; C4_PD1.1@7059.99,13470 7104,13470 ; R8_PD1.1@7080,13320 7104,13344 7104,13470
  BottomLayer w4: v1(6920,13800) v1(6920,13840)
NetC4_PD2_1: C4_PD2.1 C5_PD2.1 D2_PD2.1 R8_PD2.1 U1_PD2.6 | length 1228.8
  TopLayer w4: U1_PD2.6@7602.35,13700 7660,13700 7670,13710 7740,13710 ; v1(7660,13800) 7690,13800 7740,13750 7740,13710 ; v1(7660,13840) 7680,13840 7690,13850 7800,13850 7810,13840 D2_PD2.1@7810,13800.01 7839.99,13800.01 7844,13796 7844,13788 7844,13470 ; C5_PD2.1@7710.01,13580 7730,13600 7730,13620 7740,13630 7740,13710 ; C4_PD2.1@7799.99,13470 7844,13470 ; R8_PD2.1@7820,13320 7844,13344 7844,13470
  BottomLayer w4: v1(7660,13800) v1(7660,13840)
NetC4_PD3_1: C4_PD3.1 C5_PD3.1 D2_PD3.1 R8_PD3.1 U1_PD3.6 | length 1228.8
  TopLayer w4: U1_PD3.6@8342.35,13700 8400,13700 8410,13710 8480,13710 ; v1(8400,13800) 8430,13800 8480,13750 8480,13710 ; v1(8400,13840) 8420,13840 8430,13850 8540,13850 8550,13840 D2_PD3.1@8550,13800.01 8579.99,13800.01 8584,13796 8584,13788 8584,13470 ; C5_PD3.1@8450.01,13580 8470,13600 8470,13620 8480,13630 8480,13710 ; C4_PD3.1@8539.99,13470 8584,13470 ; R8_PD3.1@8560,13320 8584,13344 8584,13470
  BottomLayer w4: v1(8400,13800) v1(8400,13840)
NetC4_PD4_1: C4_PD4.1 C5_PD4.1 D2_PD4.1 R8_PD4.1 U1_PD4.6 | length 1228.8
  TopLayer w4: U1_PD4.6@9082.35,13700 9140,13700 9150,13710 9220,13710 ; v1(9140,13800) 9170,13800 9220,13750 9220,13710 ; v1(9140,13840) 9160,13840 9170,13850 9280,13850 9290,13840 D2_PD4.1@9290,13800.01 9319.99,13800.01 9324,13796 9324,13788 9324,13470 ; C5_PD4.1@9190.01,13580 9210,13600 9210,13620 9220,13630 9220,13710 ; C4_PD4.1@9279.99,13470 9324,13470 ; R8_PD4.1@9300,13320 9324,13344 9324,13470
  BottomLayer w4: v1(9140,13800) v1(9140,13840)
NetC4_PD5_1: C4_PD5.1 C5_PD5.1 D2_PD5.1 R8_PD5.1 U1_PD5.6 | length 1228.8
  TopLayer w4: v1(8820,13800) v1(8820,13840)
  BottomLayer w4: R8_PD5.1@8660,13320 8636,13344 8636,13470 ; C4_PD5.1@8680.01,13470 8636,13470 ; C5_PD5.1@8769.99,13580 8750,13600 8750,13620 8740,13630 8740,13710 ; v1(8820,13800) 8790,13800 8740,13750 8740,13710 ; v1(8820,13840) 8800,13840 8790,13850 8680,13850 8670,13840 D2_PD5.1@8670,13800.01 8640.01,13800.01 8636,13796 8636,13788 8636,13470 ; U1_PD5.6@8877.65,13700 8820,13700 8810,13710 8740,13710
NetC4_PD6_1: C4_PD6.1 C5_PD6.1 D2_PD6.1 R8_PD6.1 U1_PD6.6 | length 1228.8
  TopLayer w4: v1(8080,13800) v1(8080,13840)
  BottomLayer w4: R8_PD6.1@7920,13320 7896,13344 7896,13470 ; C4_PD6.1@7940.01,13470 7896,13470 ; C5_PD6.1@8029.99,13580 8010,13600 8010,13620 8000,13630 8000,13710 ; v1(8080,13800) 8050,13800 8000,13750 8000,13710 ; v1(8080,13840) 8060,13840 8050,13850 7940,13850 7930,13840 D2_PD6.1@7930,13800.01 7900.01,13800.01 7896,13796 7896,13788 7896,13470 ; U1_PD6.6@8137.65,13700 8080,13700 8070,13710 8000,13710
NetC4_PD7_1: C4_PD7.1 C5_PD7.1 D2_PD7.1 R8_PD7.1 U1_PD7.6 | length 1228.8
  TopLayer w4: v1(7340,13800) v1(7340,13840)
  BottomLayer w4: R8_PD7.1@7180,13320 7156,13344 7156,13470 ; C4_PD7.1@7200.01,13470 7156,13470 ; C5_PD7.1@7289.99,13580 7270,13600 7270,13620 7260,13630 7260,13710 ; v1(7340,13800) 7310,13800 7260,13750 7260,13710 ; v1(7340,13840) 7320,13840 7310,13850 7200,13850 7190,13840 D2_PD7.1@7190,13800.01 7160.01,13800.01 7156,13796 7156,13788 7156,13470 ; U1_PD7.6@7397.65,13700 7340,13700 7330,13710 7260,13710
NetC4_PD8_1: C4_PD8.1 C5_PD8.1 D2_PD8.1 R8_PD8.1 U1_PD8.6 | length 1228.8
  TopLayer w4: v1(6600,13800) v1(6600,13840)
  BottomLayer w4: R8_PD8.1@6440,13320 6416,13344 6416,13470 ; C4_PD8.1@6460.01,13470 6416,13470 ; C5_PD8.1@6549.99,13580 6530,13600 6530,13620 6520,13630 6520,13710 ; v1(6600,13800) 6570,13800 6520,13750 6520,13710 ; v1(6600,13840) 6580,13840 6570,13850 6460,13850 6450,13840 D2_PD8.1@6450,13800.01 6420.01,13800.01 6416,13796 6416,13788 6416,13470 ; U1_PD8.6@6657.65,13700 6600,13700 6590,13710 6520,13710
NetC4_PD9_1: C4_PD9.1 C5_PD9.1 D2_PD9.1 R8_PD9.1 U1_PD9.6 | length 1228.8
  TopLayer w4: U1_PD9.6@6862.35,14360 6920,14360 6930,14370 7000,14370 ; v1(6920,14460) 6950,14460 7000,14410 7000,14370 ; v1(6920,14500) 6940,14500 6950,14510 7060,14510 7070,14500 D2_PD9.1@7070,14460.01 7099.99,14460.01 7104,14456 7104,14448 7104,14130 ; C5_PD9.1@6970.01,14240 6990,14260 6990,14280 7000,14290 7000,14370 ; C4_PD9.1@7059.99,14130 7104,14130 ; R8_PD9.1@7080,13980 7104,14004 7104,14130
  BottomLayer w4: v1(6920,14460) v1(6920,14500)
NetC4_PD10_1: C4_PD10.1 C5_PD10.1 D2_PD10.1 R8_PD10.1 U1_PD10.6 | length 1228.8
  TopLayer w4: U1_PD10.6@7602.35,14360 7660,14360 7670,14370 7740,14370 ; v1(7660,14460) 7690,14460 7740,14410 7740,14370 ; v1(7660,14500) 7680,14500 7690,14510 7800,14510 7810,14500 D2_PD10.1@7810,14460.01 7839.99,14460.01 7844,14456 7844,14448 7844,14130 ; C5_PD10.1@7710.01,14240 7730,14260 7730,14280 7740,14290 7740,14370 ; C4_PD10.1@7799.99,14130 7844,14130 ; R8_PD10.1@7820,13980 7844,14004 7844,14130
  BottomLayer w4: v1(7660,14460) v1(7660,14500)
NetC4_PD11_1: C4_PD11.1 C5_PD11.1 D2_PD11.1 R8_PD11.1 U1_PD11.6 | length 1228.8
  TopLayer w4: U1_PD11.6@8342.35,14360 8400,14360 8410,14370 8480,14370 ; v1(8400,14460) 8430,14460 8480,14410 8480,14370 ; v1(8400,14500) 8420,14500 8430,14510 8540,14510 8550,14500 D2_PD11.1@8550,14460.01 8579.99,14460.01 8584,14456 8584,14448 8584,14130 ; C5_PD11.1@8450.01,14240 8470,14260 8470,14280 8480,14290 8480,14370 ; C4_PD11.1@8539.99,14130 8584,14130 ; R8_PD11.1@8560,13980 8584,14004 8584,14130
  BottomLayer w4: v1(8400,14460) v1(8400,14500)
NetC4_PD12_1: C4_PD12.1 C5_PD12.1 D2_PD12.1 R8_PD12.1 U1_PD12.6 | length 1228.8
  TopLayer w4: U1_PD12.6@9082.35,14360 9140,14360 9150,14370 9220,14370 ; v1(9140,14460) 9170,14460 9220,14410 9220,14370 ; v1(9140,14500) 9160,14500 9170,14510 9280,14510 9290,14500 D2_PD12.1@9290,14460.01 9319.99,14460.01 9324,14456 9324,14448 9324,14130 ; C5_PD12.1@9190.01,14240 9210,14260 9210,14280 9220,14290 9220,14370 ; C4_PD12.1@9279.99,14130 9324,14130 ; R8_PD12.1@9300,13980 9324,14004 9324,14130
  BottomLayer w4: v1(9140,14460) v1(9140,14500)
NetC4_PD13_1: C4_PD13.1 C5_PD13.1 D2_PD13.1 R8_PD13.1 U1_PD13.6 | length 1228.8
  TopLayer w4: v1(8820,14460) v1(8820,14500)
  BottomLayer w4: R8_PD13.1@8660,13980 8636,14004 8636,14130 ; C4_PD13.1@8680.01,14130 8636,14130 ; C5_PD13.1@8769.99,14240 8750,14260 8750,14280 8740,14290 8740,14370 ; v1(8820,14460) 8790,14460 8740,14410 8740,14370 ; v1(8820,14500) 8800,14500 8790,14510 8680,14510 8670,14500 D2_PD13.1@8670,14460.01 8640.01,14460.01 8636,14456 8636,14448 8636,14130 ; U1_PD13.6@8877.65,14360 8820,14360 8810,14370 8740,14370
NetC4_PD14_1: C4_PD14.1 C5_PD14.1 D2_PD14.1 R8_PD14.1 U1_PD14.6 | length 1228.8
  TopLayer w4: v1(8080,14460) v1(8080,14500)
  BottomLayer w4: R8_PD14.1@7920,13980 7896,14004 7896,14130 ; C4_PD14.1@7940.01,14130 7896,14130 ; C5_PD14.1@8029.99,14240 8010,14260 8010,14280 8000,14290 8000,14370 ; v1(8080,14460) 8050,14460 8000,14410 8000,14370 ; v1(8080,14500) 8060,14500 8050,14510 7940,14510 7930,14500 D2_PD14.1@7930,14460.01 7900.01,14460.01 7896,14456 7896,14448 7896,14130 ; U1_PD14.6@8137.65,14360 8080,14360 8070,14370 8000,14370
NetC4_PD15_1: C4_PD15.1 C5_PD15.1 D2_PD15.1 R8_PD15.1 U1_PD15.6 | length 1228.8
  TopLayer w4: v1(7340,14460) v1(7340,14500)
  BottomLayer w4: R8_PD15.1@7180,13980 7156,14004 7156,14130 ; C4_PD15.1@7200.01,14130 7156,14130 ; C5_PD15.1@7289.99,14240 7270,14260 7270,14280 7260,14290 7260,14370 ; v1(7340,14460) 7310,14460 7260,14410 7260,14370 ; v1(7340,14500) 7320,14500 7310,14510 7200,14510 7190,14500 D2_PD15.1@7190,14460.01 7160.01,14460.01 7156,14456 7156,14448 7156,14130 ; U1_PD15.6@7397.65,14360 7340,14360 7330,14370 7260,14370
NetC4_PD16_1: C4_PD16.1 C5_PD16.1 D2_PD16.1 R8_PD16.1 U1_PD16.6 | length 1228.8
  TopLayer w4: v1(6600,14460) v1(6600,14500)
  BottomLayer w4: R8_PD16.1@6440,13980 6416,14004 6416,14130 ; C4_PD16.1@6460.01,14130 6416,14130 ; C5_PD16.1@6549.99,14240 6530,14260 6530,14280 6520,14290 6520,14370 ; v1(6600,14460) 6570,14460 6520,14410 6520,14370 ; v1(6600,14500) 6580,14500 6570,14510 6460,14510 6450,14500 D2_PD16.1@6450,14460.01 6420.01,14460.01 6416,14456 6416,14448 6416,14130 ; U1_PD16.6@6657.65,14360 6600,14360 6590,14370 6520,14370
NetC4_PD17_1: C4_PD17.1 C5_PD17.1 D2_PD17.1 R8_PD17.1 U1_PD17.6 | length 1228.8
  TopLayer w4: U1_PD17.6@6862.35,15020 6920,15020 6930,15030 7000,15030 ; v1(6920,15120) 6950,15120 7000,15070 7000,15030 ; v1(6920,15160) 6940,15160 6950,15170 7060,15170 7070,15160 D2_PD17.1@7070,15120.01 7099.99,15120.01 7104,15116 7104,15108 7104,14790 ; C5_PD17.1@6970.01,14900 6990,14920 6990,14940 7000,14950 7000,15030 ; C4_PD17.1@7059.99,14790 7104,14790 ; R8_PD17.1@7080,14640 7104,14664 7104,14790
  BottomLayer w4: v1(6920,15120) v1(6920,15160)
NetC4_PD18_1: C4_PD18.1 C5_PD18.1 D2_PD18.1 R8_PD18.1 U1_PD18.6 | length 1228.8
  TopLayer w4: U1_PD18.6@7602.35,15020 7660,15020 7670,15030 7740,15030 ; v1(7660,15120) 7690,15120 7740,15070 7740,15030 ; v1(7660,15160) 7680,15160 7690,15170 7800,15170 7810,15160 D2_PD18.1@7810,15120.01 7839.99,15120.01 7844,15116 7844,15108 7844,14790 ; C5_PD18.1@7710.01,14900 7730,14920 7730,14940 7740,14950 7740,15030 ; C4_PD18.1@7799.99,14790 7844,14790 ; R8_PD18.1@7820,14640 7844,14664 7844,14790
  BottomLayer w4: v1(7660,15120) v1(7660,15160)
NetC4_PD19_1: C4_PD19.1 C5_PD19.1 D2_PD19.1 R8_PD19.1 U1_PD19.6 | length 1228.8
  TopLayer w4: U1_PD19.6@8342.35,15020 8400,15020 8410,15030 8480,15030 ; v1(8400,15120) 8430,15120 8480,15070 8480,15030 ; v1(8400,15160) 8420,15160 8430,15170 8540,15170 8550,15160 D2_PD19.1@8550,15120.01 8579.99,15120.01 8584,15116 8584,15108 8584,14790 ; C5_PD19.1@8450.01,14900 8470,14920 8470,14940 8480,14950 8480,15030 ; C4_PD19.1@8539.99,14790 8584,14790 ; R8_PD19.1@8560,14640 8584,14664 8584,14790
  BottomLayer w4: v1(8400,15120) v1(8400,15160)
NetC4_PD20_1: C4_PD20.1 C5_PD20.1 D2_PD20.1 R8_PD20.1 U1_PD20.6 | length 1228.8
  TopLayer w4: U1_PD20.6@9082.35,15020 9140,15020 9150,15030 9220,15030 ; v1(9140,15120) 9170,15120 9220,15070 9220,15030 ; v1(9140,15160) 9160,15160 9170,15170 9280,15170 9290,15160 D2_PD20.1@9290,15120.01 9319.99,15120.01 9324,15116 9324,15108 9324,14790 ; C5_PD20.1@9190.01,14900 9210,14920 9210,14940 9220,14950 9220,15030 ; C4_PD20.1@9279.99,14790 9324,14790 ; R8_PD20.1@9300,14640 9324,14664 9324,14790
  BottomLayer w4: v1(9140,15120) v1(9140,15160)
NetC4_PD21_1: C4_PD21.1 C5_PD21.1 D2_PD21.1 R8_PD21.1 U1_PD21.6 | length 1228.8
  TopLayer w4: v1(8820,15120) v1(8820,15160)
  BottomLayer w4: R8_PD21.1@8660,14640 8636,14664 8636,14790 ; C4_PD21.1@8680.01,14790 8636,14790 ; C5_PD21.1@8769.99,14900 8750,14920 8750,14940 8740,14950 8740,15030 ; v1(8820,15120) 8790,15120 8740,15070 8740,15030 ; v1(8820,15160) 8800,15160 8790,15170 8680,15170 8670,15160 D2_PD21.1@8670,15120.01 8640.01,15120.01 8636,15116 8636,15108 8636,14790 ; U1_PD21.6@8877.65,15020 8820,15020 8810,15030 8740,15030
NetC4_PD22_1: C4_PD22.1 C5_PD22.1 D2_PD22.1 R8_PD22.1 U1_PD22.6 | length 1228.8
  TopLayer w4: v1(8080,15120) v1(8080,15160)
  BottomLayer w4: R8_PD22.1@7920,14640 7896,14664 7896,14790 ; C4_PD22.1@7940.01,14790 7896,14790 ; C5_PD22.1@8029.99,14900 8010,14920 8010,14940 8000,14950 8000,15030 ; v1(8080,15120) 8050,15120 8000,15070 8000,15030 ; v1(8080,15160) 8060,15160 8050,15170 7940,15170 7930,15160 D2_PD22.1@7930,15120.01 7900.01,15120.01 7896,15116 7896,15108 7896,14790 ; U1_PD22.6@8137.65,15020 8080,15020 8070,15030 8000,15030
NetC4_PD23_1: C4_PD23.1 C5_PD23.1 D2_PD23.1 R8_PD23.1 U1_PD23.6 | length 1228.8
  TopLayer w4: v1(7340,15120) v1(7340,15160)
  BottomLayer w4: R8_PD23.1@7180,14640 7156,14664 7156,14790 ; C4_PD23.1@7200.01,14790 7156,14790 ; C5_PD23.1@7289.99,14900 7270,14920 7270,14940 7260,14950 7260,15030 ; v1(7340,15120) 7310,15120 7260,15070 7260,15030 ; v1(7340,15160) 7320,15160 7310,15170 7200,15170 7190,15160 D2_PD23.1@7190,15120.01 7160.01,15120.01 7156,15116 7156,15108 7156,14790 ; U1_PD23.6@7397.65,15020 7340,15020 7330,15030 7260,15030
NetC4_PD24_1: C4_PD24.1 C5_PD24.1 D2_PD24.1 R8_PD24.1 U1_PD24.6 | length 1228.8
  TopLayer w4: v1(6600,15120) v1(6600,15160)
  BottomLayer w4: R8_PD24.1@6440,14640 6416,14664 6416,14790 ; C4_PD24.1@6460.01,14790 6416,14790 ; C5_PD24.1@6549.99,14900 6530,14920 6530,14940 6520,14950 6520,15030 ; v1(6600,15120) 6570,15120 6520,15070 6520,15030 ; v1(6600,15160) 6580,15160 6570,15170 6460,15170 6450,15160 D2_PD24.1@6450,15120.01 6420.01,15120.01 6416,15116 6416,15108 6416,14790 ; U1_PD24.6@6657.65,15020 6600,15020 6590,15030 6520,15030
NetC4_PD25_1: C4_PD25.1 C5_PD25.1 D2_PD25.1 R8_PD25.1 U1_PD25.6 | length 1228.8
  TopLayer w4: U1_PD25.6@6862.35,15680 6920,15680 6930,15690 7000,15690 ; v1(6920,15780) 6950,15780 7000,15730 7000,15690 ; v1(6920,15820) 6940,15820 6950,15830 7060,15830 7070,15820 D2_PD25.1@7070,15780.01 7099.99,15780.01 7104,15776 7104,15768 7104,15450 ; C5_PD25.1@6970.01,15560 6990,15580 6990,15600 7000,15610 7000,15690 ; C4_PD25.1@7059.99,15450 7104,15450 ; R8_PD25.1@7080,15300 7104,15324 7104,15450
  BottomLayer w4: v1(6920,15780) v1(6920,15820)
NetC4_PD26_1: C4_PD26.1 C5_PD26.1 D2_PD26.1 R8_PD26.1 U1_PD26.6 | length 1228.8
  TopLayer w4: U1_PD26.6@7602.35,15680 7660,15680 7670,15690 7740,15690 ; v1(7660,15780) 7690,15780 7740,15730 7740,15690 ; v1(7660,15820) 7680,15820 7690,15830 7800,15830 7810,15820 D2_PD26.1@7810,15780.01 7839.99,15780.01 7844,15776 7844,15768 7844,15450 ; C5_PD26.1@7710.01,15560 7730,15580 7730,15600 7740,15610 7740,15690 ; C4_PD26.1@7799.99,15450 7844,15450 ; R8_PD26.1@7820,15300 7844,15324 7844,15450
  BottomLayer w4: v1(7660,15780) v1(7660,15820)
NetC4_PD27_1: C4_PD27.1 C5_PD27.1 D2_PD27.1 R8_PD27.1 U1_PD27.6 | length 1228.8
  TopLayer w4: U1_PD27.6@8342.35,15680 8400,15680 8410,15690 8480,15690 ; v1(8400,15780) 8430,15780 8480,15730 8480,15690 ; v1(8400,15820) 8420,15820 8430,15830 8540,15830 8550,15820 D2_PD27.1@8550,15780.01 8579.99,15780.01 8584,15776 8584,15768 8584,15450 ; C5_PD27.1@8450.01,15560 8470,15580 8470,15600 8480,15610 8480,15690 ; C4_PD27.1@8539.99,15450 8584,15450 ; R8_PD27.1@8560,15300 8584,15324 8584,15450
  BottomLayer w4: v1(8400,15780) v1(8400,15820)
NetC4_PD28_1: C4_PD28.1 C5_PD28.1 D2_PD28.1 R8_PD28.1 U1_PD28.6 | length 1228.8
  TopLayer w4: U1_PD28.6@9082.35,15680 9140,15680 9150,15690 9220,15690 ; v1(9140,15780) 9170,15780 9220,15730 9220,15690 ; v1(9140,15820) 9160,15820 9170,15830 9280,15830 9290,15820 D2_PD28.1@9290,15780.01 9319.99,15780.01 9324,15776 9324,15768 9324,15450 ; C5_PD28.1@9190.01,15560 9210,15580 9210,15600 9220,15610 9220,15690 ; C4_PD28.1@9279.99,15450 9324,15450 ; R8_PD28.1@9300,15300 9324,15324 9324,15450
  BottomLayer w4: v1(9140,15780) v1(9140,15820)
NetC4_PD29_1: C4_PD29.1 C5_PD29.1 D2_PD29.1 R8_PD29.1 U1_PD29.6 | length 1228.8
  TopLayer w4: v1(8820,15780) v1(8820,15820)
  BottomLayer w4: R8_PD29.1@8660,15300 8636,15324 8636,15450 ; C4_PD29.1@8680.01,15450 8636,15450 ; C5_PD29.1@8769.99,15560 8750,15580 8750,15600 8740,15610 8740,15690 ; v1(8820,15780) 8790,15780 8740,15730 8740,15690 ; v1(8820,15820) 8800,15820 8790,15830 8680,15830 8670,15820 D2_PD29.1@8670,15780.01 8640.01,15780.01 8636,15776 8636,15768 8636,15450 ; U1_PD29.6@8877.65,15680 8820,15680 8810,15690 8740,15690
NetC4_PD30_1: C4_PD30.1 C5_PD30.1 D2_PD30.1 R8_PD30.1 U1_PD30.6 | length 1228.8
  TopLayer w4: v1(8080,15780) v1(8080,15820)
  BottomLayer w4: R8_PD30.1@7920,15300 7896,15324 7896,15450 ; C4_PD30.1@7940.01,15450 7896,15450 ; C5_PD30.1@8029.99,15560 8010,15580 8010,15600 8000,15610 8000,15690 ; v1(8080,15780) 8050,15780 8000,15730 8000,15690 ; v1(8080,15820) 8060,15820 8050,15830 7940,15830 7930,15820 D2_PD30.1@7930,15780.01 7900.01,15780.01 7896,15776 7896,15768 7896,15450 ; U1_PD30.6@8137.65,15680 8080,15680 8070,15690 8000,15690
NetC4_PD31_1: C4_PD31.1 C5_PD31.1 D2_PD31.1 R8_PD31.1 U1_PD31.6 | length 1228.8
  TopLayer w4: v1(7340,15780) v1(7340,15820)
  BottomLayer w4: R8_PD31.1@7180,15300 7156,15324 7156,15450 ; C4_PD31.1@7200.01,15450 7156,15450 ; C5_PD31.1@7289.99,15560 7270,15580 7270,15600 7260,15610 7260,15690 ; v1(7340,15780) 7310,15780 7260,15730 7260,15690 ; v1(7340,15820) 7320,15820 7310,15830 7200,15830 7190,15820 D2_PD31.1@7190,15780.01 7160.01,15780.01 7156,15776 7156,15768 7156,15450 ; U1_PD31.6@7397.65,15680 7340,15680 7330,15690 7260,15690
NetC4_PD32_1: C4_PD32.1 C5_PD32.1 D2_PD32.1 R8_PD32.1 U1_PD32.6 | length 1228.8
  TopLayer w4: v1(6600,15780) v1(6600,15820)
  BottomLayer w4: R8_PD32.1@6440,15300 6416,15324 6416,15450 ; C4_PD32.1@6460.01,15450 6416,15450 ; C5_PD32.1@6549.99,15560 6530,15580 6530,15600 6520,15610 6520,15690 ; v1(6600,15780) 6570,15780 6520,15730 6520,15690 ; v1(6600,15820) 6580,15820 6570,15830 6460,15830 6450,15820 D2_PD32.1@6450,15780.01 6420.01,15780.01 6416,15776 6416,15768 6416,15450 ; U1_PD32.6@6657.65,15680 6600,15680 6590,15690 6520,15690
NetC5_PD1_2: C5_PD1.2 R8_PD1.2 R88_PD1.1 U1_PD1.9 | length 921.1
  TopLayer w4: U1_PD1.9@6657.63,13700 6715,13700 6735,13680 6933,13680 ; R88_PD1.1@6970,13680 6933,13680 ; C5_PD1.2@7060.01,13580 7025,13580 7020,13575 7020,13430 ; R8_PD1.2@7080,13375 7025,13430 7020,13430 ; 6933,13680 6933,13441 6944,13430 7020,13430
NetC5_PD2_2: C5_PD2.2 R8_PD2.2 R88_PD2.1 U1_PD2.9 | length 921.1
  TopLayer w4: U1_PD2.9@7397.63,13700 7455,13700 7475,13680 7673,13680 ; R88_PD2.1@7710,13680 7673,13680 ; C5_PD2.2@7800.01,13580 7765,13580 7760,13575 7760,13430 ; R8_PD2.2@7820,13375 7765,13430 7760,13430 ; 7673,13680 7673,13441 7684,13430 7760,13430
NetC5_PD3_2: C5_PD3.2 R8_PD3.2 R88_PD3.1 U1_PD3.9 | length 921.1
  TopLayer w4: U1_PD3.9@8137.63,13700 8195,13700 8215,13680 8413,13680 ; R88_PD3.1@8450,13680 8413,13680 ; C5_PD3.2@8540.01,13580 8505,13580 8500,13575 8500,13430 ; R8_PD3.2@8560,13375 8505,13430 8500,13430 ; 8413,13680 8413,13441 8424,13430 8500,13430
NetC5_PD4_2: C5_PD4.2 R8_PD4.2 R88_PD4.1 U1_PD4.9 | length 921.1
  TopLayer w4: U1_PD4.9@8877.63,13700 8935,13700 8955,13680 9153,13680 ; R88_PD4.1@9190,13680 9153,13680 ; C5_PD4.2@9280.01,13580 9245,13580 9240,13575 9240,13430 ; R8_PD4.2@9300,13375 9245,13430 9240,13430 ; 9153,13680 9153,13441 9164,13430 9240,13430
NetC5_PD5_2: C5_PD5.2 R8_PD5.2 R88_PD5.1 U1_PD5.9 | length 921.1
  BottomLayer w4: R8_PD5.2@8660,13375 8715,13430 8720,13430 ; C5_PD5.2@8679.99,13580 8715,13580 8720,13575 8720,13430 ; R88_PD5.1@8770,13680 8807,13680 ; U1_PD5.9@9082.37,13700 9025,13700 9005,13680 8807,13680 ; 8720,13430 8796,13430 8807,13441 8807,13680
NetC5_PD6_2: C5_PD6.2 R8_PD6.2 R88_PD6.1 U1_PD6.9 | length 921.1
  BottomLayer w4: R8_PD6.2@7920,13375 7975,13430 7980,13430 ; C5_PD6.2@7939.99,13580 7975,13580 7980,13575 7980,13430 ; R88_PD6.1@8030,13680 8067,13680 ; U1_PD6.9@8342.37,13700 8285,13700 8265,13680 8067,13680 ; 7980,13430 8056,13430 8067,13441 8067,13680
NetC5_PD7_2: C5_PD7.2 R8_PD7.2 R88_PD7.1 U1_PD7.9 | length 921.1
  BottomLayer w4: R8_PD7.2@7180,13375 7235,13430 7240,13430 ; C5_PD7.2@7199.99,13580 7235,13580 7240,13575 7240,13430 ; R88_PD7.1@7290,13680 7327,13680 ; U1_PD7.9@7602.37,13700 7545,13700 7525,13680 7327,13680 ; 7240,13430 7316,13430 7327,13441 7327,13680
